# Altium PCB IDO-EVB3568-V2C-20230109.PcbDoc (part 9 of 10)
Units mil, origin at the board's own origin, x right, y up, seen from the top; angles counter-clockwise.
Board outline 5318 x 3544 mil, 2 copper layers (TOP, BOTTOM), stack 6.8 mil thick; 790 components, 626 nets, 2890 pads, 1922 vias.
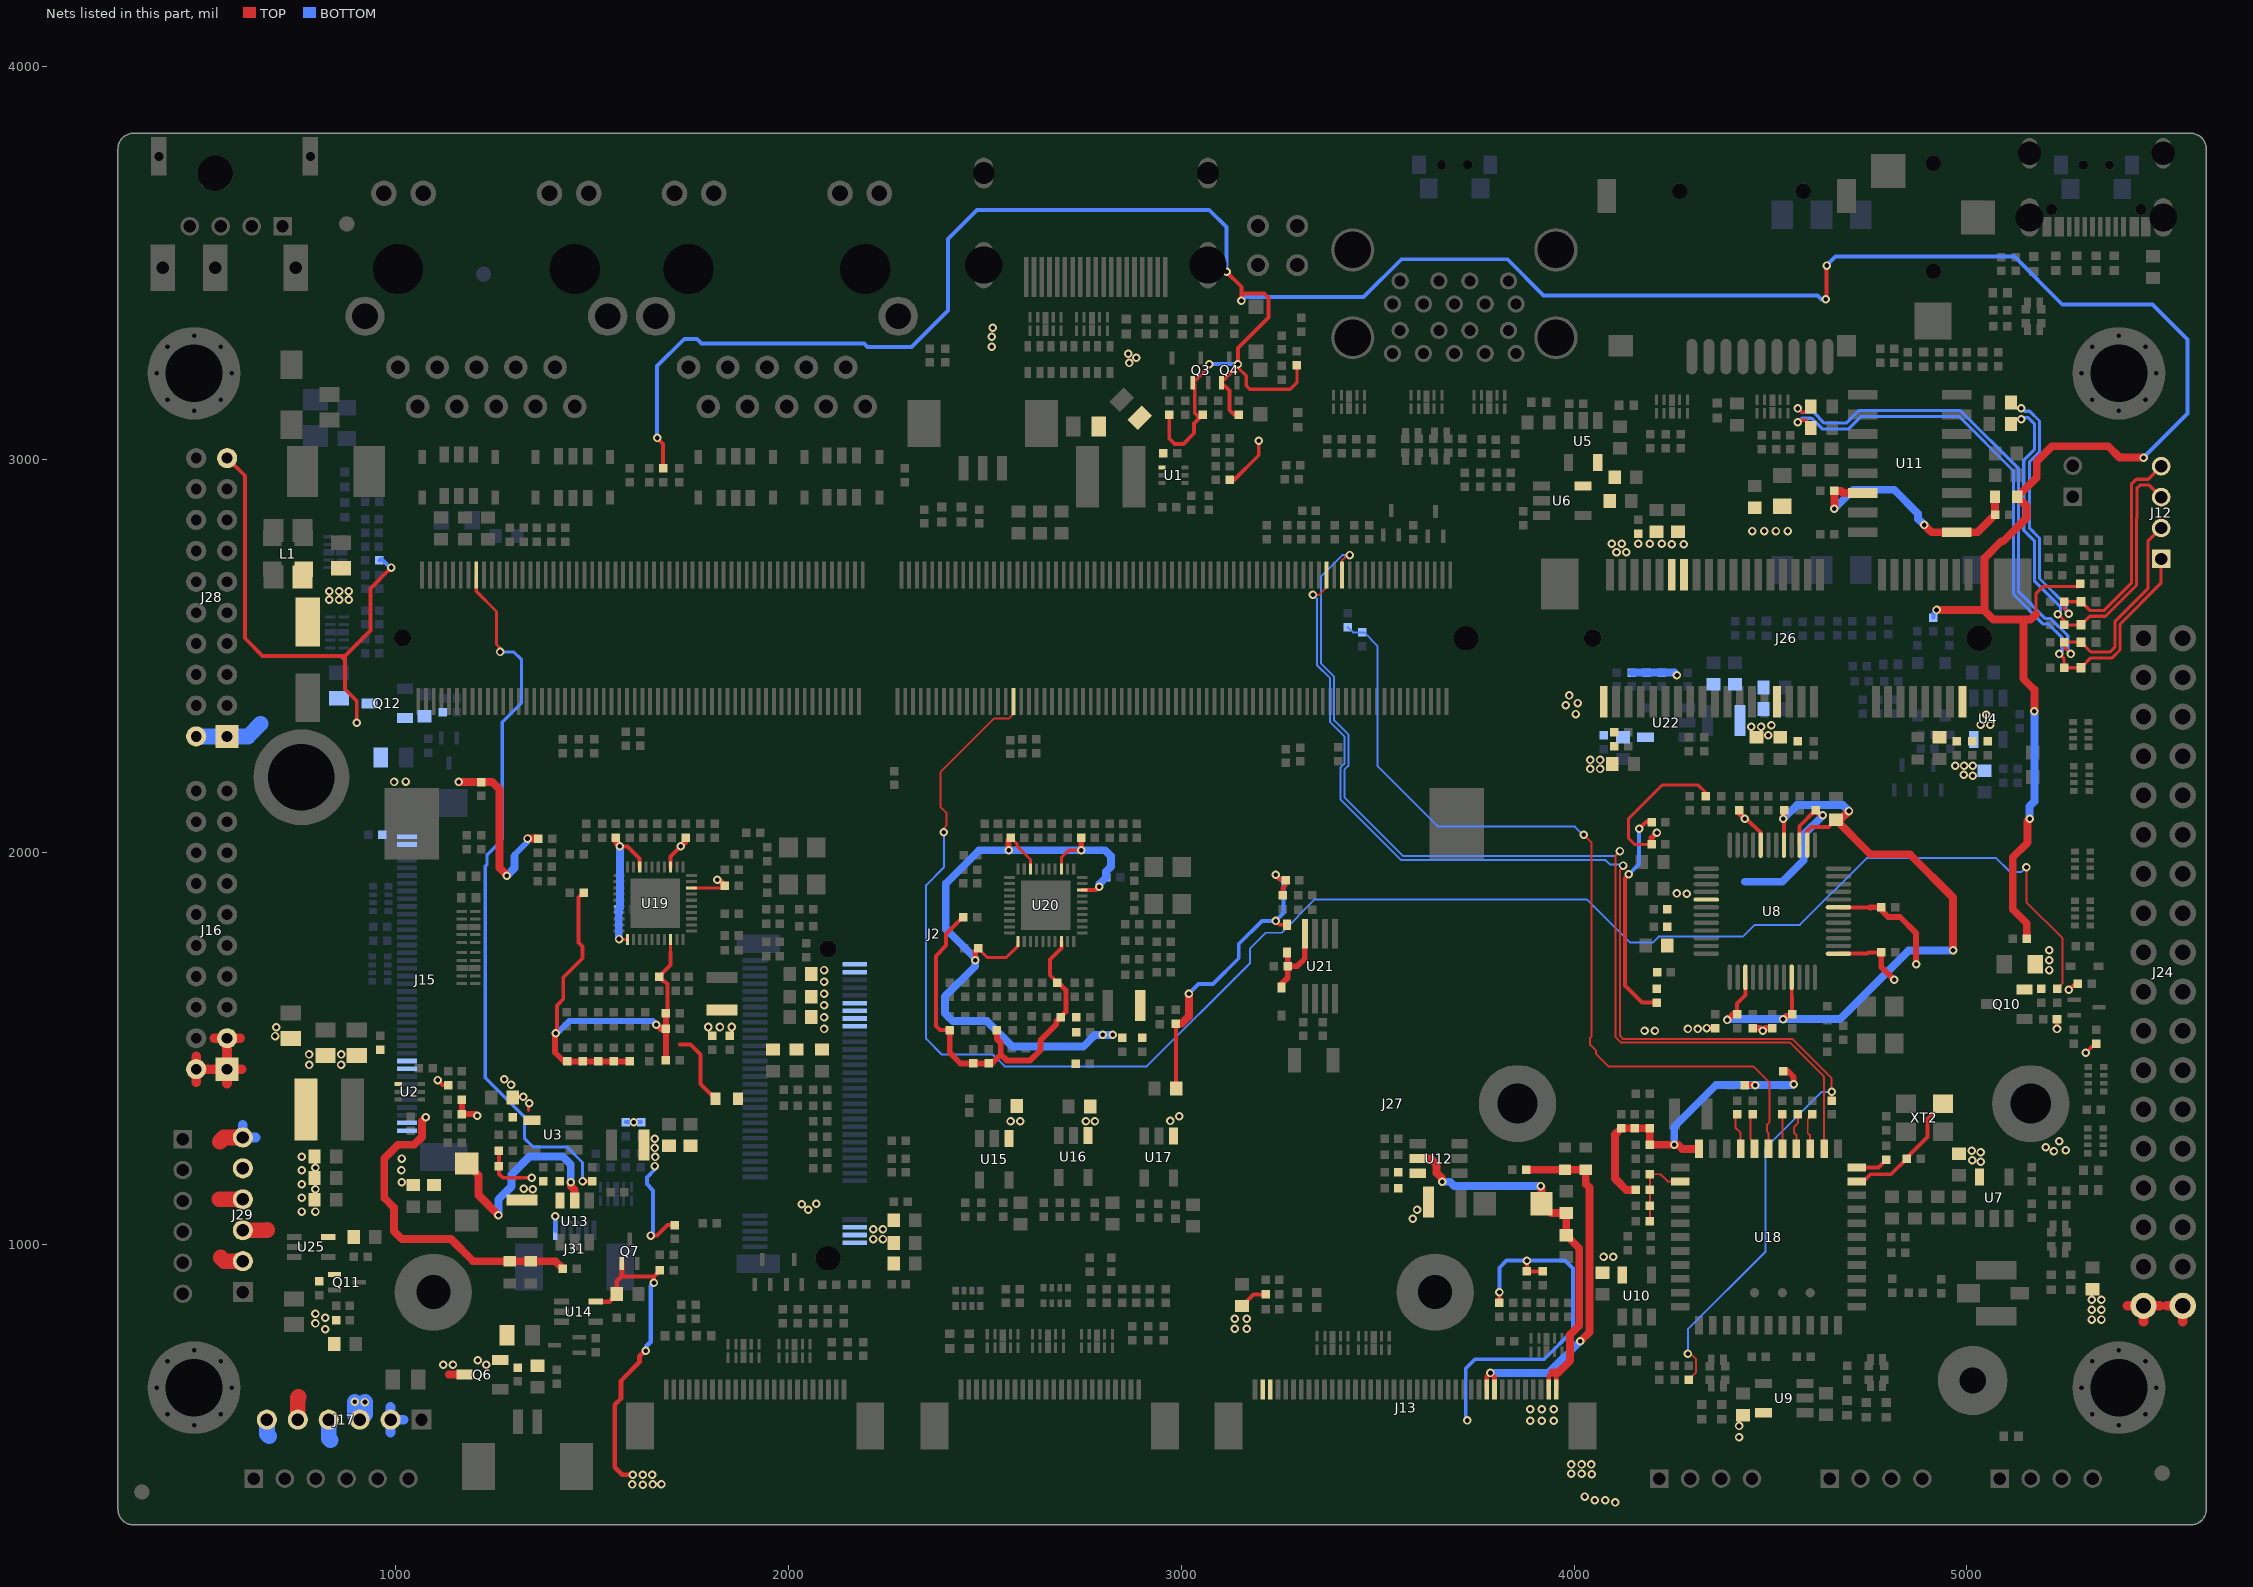
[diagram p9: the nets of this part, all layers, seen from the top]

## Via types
v1: diameter 21.65, hole 11.81, TOP to BOTTOM, 1878 vias
v2: diameter 17.72, hole 7.87, TOP to BOTTOM, 44 vias

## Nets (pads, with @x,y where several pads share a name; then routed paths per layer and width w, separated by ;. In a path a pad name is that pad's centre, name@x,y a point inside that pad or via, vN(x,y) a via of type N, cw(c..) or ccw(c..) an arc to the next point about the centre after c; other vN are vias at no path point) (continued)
VCC_1V8_HUB: C50.2 C60.2 C61.2 C62.2 U8.3 U8.9 U8.26 U8.29 | length 1861.5
  TOP w10: C61.2@4415,1587.72 4415,1615 4436.1,1636.1 U8.3@4436.1,1681.7 ; v1(4532.5,2085) 4534.5,2083 U8.29@4534.5,2018.3 ; U8.9@4554.2,1681.7 4554.2,1630.8 4555,1630 C60.2@4555,1587.72 ; U8.26@4593.6,2018.3 4593.6,2053.6 4604,2064 4648.56,2064 C50.2@4667,2082.44
  TOP w15: v1(4390,1573) 4404.72,1587.72 C61.2@4415,1587.72 ; v1(4532,1575) 4540,1583 4550.28,1583 C60.2@4555,1587.72 ; v1(4532.5,2085) 4535,2087.5 C62.2@4535,2107.28
  TOP w20: v1(4700,2105) 4677.44,2082.44 C50.2@4667,2082.44 4754.44,1995 4855,1995 4965,1885 v1(4965,1750)
  BOTTOM w20: v1(4390,1573) 4392,1575 v1(4532,1575) 4677,1575 4852,1750 v1(4965,1750) ; v1(4532.5,2085) 4567.5,2120 4685,2120 v1(4700,2105)
VCC_3V3: J2.245 R14.1 | length 1829
  TOP w8: J2.245@1204.33,2706.42 1204.33,2664.67 1256,2613 1256,2529 1265,2520 v1(1265,2510) ; v1(1475,1162.28) R14.1@1500,1162.28
  BOTTOM w8: v1(1265,2510) 1300,2510 1320,2490 1320,2381 1270.5,2331.5 1270.5,2032.52 1232,1994.02 1232,1969 1227.17,1964.17 1227.17,1425.83 1327,1326 1327,1272 1350,1249 1436,1249 1475,1210 v1(1475,1162.28)
VCC_3V3_HUB: C54.2 C55.2 C56.2 C57.2 C58.2 C59.2 R54.2 R55.2 R58.2 R59.1 R61.2 R65.1 R66.2 R76.2 U8.13 U8.19 U8.27 U8.32 U8.41 | length 1530.9
  TOP w8: R65.1@4197.28,2020 4154,2020 4139,2035 4139,2086 4224,2171 4316,2171 4335,2152 R66.2@4335,2142.72
  TOP w10: v1(4435,2085) 4439,2085 4475.5,2048.5 U8.32@4475.5,2018.3 ; U8.27@4573.9,2018.3 4573.9,2066.18 C58.2@4615,2107.28 ; U8.13@4673.3,1741.7 4746.7,1741.7 4750,1745 C57.2@4782.28,1745 ; U8.19@4673.3,1859.8 4754,1859.8
  TOP w15: R65.1@4197.28,2020 4197.28,2036.28 v1(4211,2050) ; v1(4337.72,1552.28) R58.2@4360,1552.28 ; C55.2@4420,2107.28 4420,2100 v1(4435,2085) ; R54.2@4455,1552.28 4472.72,1552.28 v1(4480,1545) 4487.28,1552.28 R55.2@4505,1552.28 ; C58.2@4615,2107.28 4628.14,2094.14 v1(4633.14,2094.14) ; 4754,1859.8 4755,1859.8 4755.2,1860 C59.2@4782.28,1860 4782.28,1852.72 4800,1835 4830,1835 4871,1794 v1(4871,1715) ; C57.2@4782.28,1745 4782.28,1707.72 v1(4815,1675)
  BOTTOM w20: 4435,1925 4530,1925 4585,1980 4585,2045 4633.14,2093.14 v1(4633.14,2094.14)
  other v1: 4290,1550 4315,1550 4287,1894 4261,1895
VCC_3V8: C190.2 C191.2 C192.2 C193.2 C194.2 C195.2 C196.2 C197.2 C198.2 C199.2 C200.2 C201.2 C202.2 C203.2 C204.2 C207.2 C208.2 C209.2 J26.2 J26.24 J26.39 J26.41 J26.52 L24.2 R342.2 R343.2 | length 117.8
  BOTTOM w20: C207.2@4147,2457.72 R343.2@4185,2457.72 C203.2@4223,2457.72 4255.28,2457.72 v1(4262,2451)
  other v1: 4041,2212 4066,2212 4041,2235 4066,2235 4494,2298 4451,2320 4476,2320 4502.65,2323.44 5035,2325 5060,2325 5050,2350 4249,2784 4279,2784 4163,2786 4193,2786 4223,2786
VCC_5V: C17.2 C18.2 C19.2 C20.2 C22.2 C23.2 C33.1 C37.1 C40.1 C43.1 C47.1 C53.1 C82.2 C83.2 C88.2 C89.2 C94.2 C177.1 C205.2 C206.2 C244.2 C248.2 J17.3 J24.35 J24.36 J29.3 L3.2 L15.1 L20.1 Q7.1 Q11.1 R11.2 R86.1 R133.1 R388.1 U3.4 U4.5 U5.5 U6.5 U7.5 U9.5 U10.5 U12.6 U13.6 U14.5 U22.4 U25.5 | length 1322.3
  TOP w5: C22.2@1297.56,1375 1322,1375 v1(1324,1377)
  TOP w8: 1337,1342 1337,1359 v1(1339,1361)
  TOP w10: 1575.32,920 1657.28,920 ; v1(1657,904) 1657,919.72 1657.28,920 ; R133.1@1672.28,935 1657.28,920
  TOP w12: U14.5@1508.31,855.59 1543.59,855.59 1562.44,874.44 C94.2@1562.44,875 1562.44,907.12 1575.32,920 Q7.1@1575.32,952.5 ; v1(1603,415) 1576,415 1557,434 1557,593 1573,609 1573,654 1620,701 1620,716 1632,728 1633.74,728 v1(1636.24,730.5)
  TOP w15: R11.2@1167.72,1333 C17.2@1167.72,1370 ; R11.2@1167.72,1333 1203.03,1332.97 v1(1207,1329)
  TOP w25: 5409.53,845 J24.35@5450,845 ; 5450,804.53 J24.35@5450,845 ; 5490.47,845 J24.35@5450,845 ; 5509.53,845 J24.36@5550,845 5550,804.53
  TOP w40: J29.3@610,1037.48 671.48,1037.48 672,1038
  BOTTOM w12: v1(1636.24,730.5) 1637,731.26 1637,742 1649,754 1649,896 v1(1657,904)
  BOTTOM w40: v1(895,601) 895,567.52 J17.3@907.52,555 921,568.48 v1(921,600)
  other v1: 1628,389 1602,390 1654,390 1676,391 1628,415 1653,415 4045,416 3993,417 4019,417 3993,441 4019,441 4044,441 4420,510 4420,539 3888,552 3918,552 3948,552 3888,582 3918,582 3948,582 5318,810 5343,810 5318,835 5343,835 5318,860 5343,860 4075,970 4100,970 3589,1067 760,1085 795,1085 3600,1090 760,1120 795,1142 1348,1142 1325,1143 760,1155 760,1190 795,1197 5036,1212 5014,1216 760,1225 5035,1236 5013,1240 1293,1408 1276,1422 5015,2195 4992,2197 4971,2220 4993,2220 5015,2220 4004,2352 3979,2374 4009,2380 3987.43,2399.29 4108,2764 4133,2764 4096,2786 4121,2786 4454,2818 4484,2818 4514,2818 4544,2818
VCC_12V: C3.1 C4.2 C5.2 C6.2 C7.2 C14.2 C15.2 C16.2 L1.4 R1.2 R3.2 U1.1 U2.1 | length 137.6
  TOP w10: R3.2@3122.72,2948 3134,2948 3197,3011 3197,3047.71 v1(3197.34,3048.05)
  other v1: 779.56,1458.35 860,1459 778.58,1485 861,1485 830,2643 855,2643 880,2643 830,2665 855,2665 880,2665 2867,3246 2885,3259 2865,3269 2517,3287 2517,3313 2520,3336
VCC_EDP_OUT: C245.2 C246.2 J29.2 J29.4 J29.6 Q12.2 R391.2 | length 248.5
  TOP w40: 550,1116 550.22,1116.22 J29.4@610,1116.22 ; 551,1263 561.7,1273.7 J29.6@610,1273.7 ; 554,968 563.26,958.74 J29.2@610,958.74
  BOTTOM w25: 610,1306.29 J29.6@610,1273.7 642.59,1273.7
VCC_EDP_OUT_: C247.2 J28.1 J28.2 Q12.3 | length 177
  BOTTOM w40: J28.2@491.26,2295 J28.1@570,2295 623,2295 655,2327
VCC_LEDA_TX0: C86.2 C87.2 D50.C J15.1 J15.2 U13.5 | length 556
  TOP w20: D50.C@1180,1207.44 1210,1177.44 1210,1127 v1(1261,1076) ; v1(1445,1160) 1445,1150 1455,1140 U13.5@1455,1113.15
  BOTTOM w20: v1(1261,1076) 1261,1116 1294,1149 1294,1179 1340,1225 1425,1225 1445,1205 v1(1445,1160)
  other v1: 1015,1160 1014,1190 1015,1220
VCC_LEDA_TX1: C81.2 C84.2 D39.C J13.1 J13.2 U12.5 | length 1029.2
  TOP w12: J13.2@3935.24,632.01 3935.24,665.16 3945.08,675 3954.92,665.16 J13.1@3954.92,632.01
  TOP w20: U12.5@3601.85,1220 3635,1220 3650,1205 3650,1183.3 3664,1169.3 v1(3664,1161) ; v1(3915,1150) 3917.44,1147.56 D39.C@3917.44,1105 3941,1081.44 C84.2@3980,1081.44 C81.2@3980,1024.56 4013,991.56 4013,795 3990,772 3990,705 3960,675 3945.08,675
  BOTTOM w20: v1(3664,1161) 3684,1161 3695,1150 v1(3915,1150)
VCC_LEDK_TX0: J15.9 J15.10 R117.1 R119.2 R120.2 | length 836.9
  TOP w20: v1(1076,1325) 1066,1315 1066,1275 1046,1255 1005,1255 970,1220 970,1120 995,1095 995,1035 1015,1015 1140,1015 1196.46,958.54 R119.2@1290,958.54 R120.2@1343,958.54 1405.74,958.54 R117.1@1424.28,940
VCC_LEDK_TX1: J13.9 J13.10 R99.1 R101.2 R102.2 | length 956.6
  TOP w12: J13.10@3777.76,632.01 3777.76,664.76 v1(3787,674) 3797.44,663.56 J13.9@3797.44,632.01
  TOP w20: R99.1@3877.72,1191 3878.18,1191.46 R102.2@3977,1191.46 R101.2@4029.52,1191.46 4029.52,1155.48 4039,1146 4039,778 v1(4016,755)
  BOTTOM w20: v1(3787,674) 3935,674 v1(4016,755)
VCC_LVDS_OUT: C91.2 C92.2 J17.2 J17.4 J17.6 Q6.2 R134.2 | length 195.9
  BOTTOM w25: 986.26,522.41 J17.2@986.26,555 ; 986.26,587.59 J17.2@986.26,555 ; 1018.85,555 J17.2@986.26,555
  BOTTOM w40: J17.6@671.3,555 671.3,518.7 677,513 ; J17.4@828.78,555 828.78,507.22 833,503
  other v1: 1230,695 1208,706
VCC_LVDS_OUT_: C93.2 J16.1 J16.2 J16.3 Q6.3 | length 381.4
  TOP w20: 1135,670 Q6.3@1174.72,670
  TOP w25: 491.26,1415.01 J16.2@491.26,1447.6 ; 491.26,1480.19 J16.2@491.26,1447.6 ; 523.85,1447.6 J16.2@491.26,1447.6 ; 533.47,1447.6 J16.1@570,1447.6 ; 537.41,1526.34 J16.3@570,1526.34 ; 570,1411.07 J16.1@570,1447.6 ; 570,1484.13 J16.1@570,1447.6 ; 570,1493.74 J16.3@570,1526.34 ; 602.59,1526.34 J16.3@570,1526.34 ; 606.53,1447.6 J16.1@570,1447.6
  other v1: 1120,695 1145,695 692,1532 695,1554
VCCA_CODEC: C67.2 C68.2 R85.2 U11.6 U11.9 | length 665.3
  TOP w20: v1(4662.72,2875) C67.2@4662.72,2920 4680,2920 4685.23,2914.78 4702.49,2914.78 4702.72,2915 U11.6@4735,2915 ; v1(4891.5,2833.5) 4910,2815 U11.9@4975,2815 5027.28,2815 C68.2@5072.28,2860 5071.46,2860.82 R85.2@5071.46,2905
  BOTTOM w20: v1(4662.72,2875) 4710.72,2923 4815,2923 4876,2862 4876,2849 v1(4891.5,2833.5)
VCCIO_PHY0: C144.2 C145.2 C146.2 R236.2 R238.2 R240.2 R243.2 R246.2 R249.2 R250.2 U19.28 | length 1277.4
  TOP w8: 1699.37,1745 U19.28@1699.37,1777.48
  TOP w10: v1(1407,1539) 1407,1547 1410,1550 1410,1610 1426,1626 1426,1681 1475,1730 1475,1760 1465,1770 1465,1884.28 R249.2@1477.72,1897 ; C145.2@1687.28,1590 1691,1593.72 1691,1664 1682.5,1672.5 1680.22,1672.5 C146.2@1670,1682.72 1670,1683.72 1699.37,1713.09 1699.37,1745
  TOP w15: v1(1407,1539) 1405,1537 1405,1490 1427.72,1467.28 R236.2@1436,1467.28 R246.2@1475,1467.28 R243.2@1515,1467.28 R240.2@1555,1467.28 R238.2@1595,1467.28 ; v1(1663,1561) 1674,1550 C144.2@1687.28,1550 ; R250.2@1687.28,1470 C144.2@1687.28,1550 ; C145.2@1687.28,1590 C144.2@1687.28,1550
  BOTTOM w15: v1(1407,1539) 1413,1545 1416,1545 1441,1570 1654,1570 v1(1663,1561)
VCCIO_PHY1: C168.1 C169.2 C170.2 R283.2 R285.2 R288.2 R291.2 R294.2 R297.2 R298.2 U20.28 | length 1072.2
  TOP w10: R283.2@2410,1547.28 2385.72,1547.28 2375,1558 2375,1736 2401,1762 2401,1791.72 R297.2@2444.28,1835 ; C170.2@2684,1667.72 2665,1686.72 2665,1727 2694.37,1756.37 U20.28@2694.37,1772.48
  TOP w12: C170.2@2684,1667.72 2687.28,1667.72 2706,1649 2706,1593.28 R285.2@2692.72,1580
  TOP w15: R283.2@2410,1547.28 2410,1490 2437.72,1462.28 R294.2@2470,1462.28 R291.2@2510,1462.28 2517.28,1462.28 2540,1485 ; R288.2@2530,1547.28 2530,1525 2540,1515 2540,1485 ; R285.2@2692.72,1580 2681.35,1568.63 2681.35,1561.35 2641,1521 2641,1496 2615,1470 2555,1470 2540,1485
VCCIO_WL: C120.2 C121.2 C122.2 R180.1 R185.1 R200.2 R204.1 U18.22 | length 918.4
  TOP w15: R180.1@4434.72,1407 v1(4461.37,1407) ; R185.1@4532,1442.72 4544,1442.72 4559,1427.72 v1(4559,1409)
  TOP w20: R204.1@4157.28,1140 4133,1140 4104,1169 4104,1281.28 R200.2@4120,1297.28 C122.2@4155,1297.28 C120.2@4193,1297.28 4192.72,1297 C121.2@4192.72,1255 v1(4255,1255) 4265,1255 4275.59,1244.41 U18.22@4317.83,1244.41
  BOTTOM w20: v1(4255,1255) 4255,1301 4361,1407 v1(4461.37,1407) 4557,1407 v1(4559,1409)
VDD3V3_PCIE30: C214.2 C215.2 C216.2 C217.2 C218.2 C219.2 C220.2 C221.2 C222.2 J27.2 J27.4 J27.12 J27.14 J27.16 J27.18 J27.70 J27.72 J27.74 R359.2
  other v1: 2215,1015 2240,1015 2215,1040 2240,1040 2050,1090 2033,1104 2070,1105 2090,1550 2090,1580 2090,1610 2090,1640 2090,1670 2090,1700
VDD10_PHY0: C136.2 C137.2 C138.2 C139.2 C140.2 C141.2 L22.2 U19.3 U19.8 U19.21 U19.38 | length 574.1
  TOP w8: v1(1568,1779) 1569,1779 1570.52,1777.48 U19.21@1589.13,1777.48 ; U19.38@1752.52,1909.37 1831.65,1909.37 C139.2@1837.28,1915
  TOP w10: v1(1570,2015) 1590,2015 1620.63,1984.37 U19.8@1620.63,1962.52 ; U19.3@1699.37,1962.52 1699.37,1989.37 v1(1725,2015)
  TOP w15: C140.2@1560,2037.28 1560,2025 v1(1570,2015) ; v1(1725,2015) 1738,2028 C141.2@1738,2037.28 ; v1(1818,1930) 1822.28,1930 C139.2@1837.28,1915
  BOTTOM w20: v1(1568,1779) 1567.28,1779.72 C138.2@1567.28,1855 1570,1857.72 v1(1570,2015)
  other v1: 1795,1555 1825,1555 1855,1555
VDD10_PHY1: C160.2 C161.2 C162.2 C163.2 C164.1 C165.2 L23.2 U20.3 U20.8 U20.21 U20.38 | length 1888.3
  TOP w8: C162.2@2482.72,1755 2505.72,1732 2554,1732 2584.13,1762.13 U20.21@2584.13,1772.48 ; C165.2@2566,2037.28 2581.14,2022.14 2581.14,2016.14 2615.63,1981.65 U20.8@2615.63,1957.52 ; U20.3@2694.37,1957.52 2694.37,1986.65 2712.72,2005 v1(2745,2005)
  TOP w10: U20.38@2747.52,1904.37 2783.37,1904.37 v1(2791,1912)
  TOP w15: v1(2475,1725) 2475,1747.28 C162.2@2482.72,1755 ; v1(2560,2005) 2560,2031.28 C165.2@2566,2037.28 ; v1(2745,2005) C164.1@2745,2037.28
  BOTTOM w20: v1(2791,1912) 2791,1918.72 C163.2@2808.28,1936 2808.28,1951.28 2820.64,1963.64 2820.64,1990 2805.64,2005 v1(2745,2005) v1(2560,2005) 2485,2005 2400,1920 2400,1805 2475,1730 v1(2475,1725) 2475,1710 2398,1633 2398,1590 2418,1570 2505,1570 2570,1505 2750,1505 2780,1535 v1(2800,1535) v1(2825,1535)
VDD_3V3: C21.2 C24.2 C25.2 C79.2 C101.2 C105.2 C109.2 C123.2 C124.2 C243.2 C260.2 D69.A J13.38 J13.39 J15.38 J15.39 J17.5 J28.19 J29.5 J31.1 L4.2 Q3.1 Q4.1 Q10.2 R10.1 R15.2 R37.2 R74.2 R76.1 R80.1 R85.1 R92.2 R93.2 R98.1 R103.1 R105.1 R109.2 R111.2 R112.2 R121.1 R132.1 R202.1 R203.2 R258.1 R267.2 R306.1 R326.2 R327.2 R359.1 R384.1 R387.1 R400.1 R401.1 R409.1 R415.1 U15.1 U16.1 U17.1 | length 13477.3
  TOP w8: v1@3144,3239.59 3144,3234 3165,3213 3165,3188 3174,3179 3277,3179 3294,3196 R10.1@3294,3240.28 ; 5176,2606 5176,2658 5195,2677 R80.1@5282.28,2677
  TOP w10: J28.19@570,3003.66 615,2958.66 615,2545 660,2500 860,2500 ; v1(900,2330) 900,2385 870,2415 870,2490 ; v1(988,2725) 935,2672 935,2565 870,2500 ; v1(1106,1420) 1118.72,1407.28 R409.1@1133,1407.28 ; R15.2@1262.28,1240 C24.2@1262.28,1200 1262.28,1180.83 1272,1171.11 v1(1346,1171.11) ; v1(1649,1024) 1665,1024 1691.72,1050.72 R132.1@1710,1050.72 ; v1(1665,3055) 1680,3040 R267.2@1680,2977.72 ; 1722.72,1510 1750,1510 1775,1485 1775,1410 R359.1@1810,1375 ; R109.2@2969,3114.28 2969,3054 2983,3040 3005,3040 3032,3067 3032,3091.28 R103.1@3046.53,3105.81 ; R306.1@2986,1563.28 2986.56,1562.72 C109.2@2986.56,1398 ; R103.1@3055,3114.28 R103.1@3046.53,3105.81 ; v1(3071,3243) 3071,3237.19 Q3.1@3029.32,3195.5 3034,3190.82 3034,3118.35 R103.1@3046.53,3105.81 ; v1(3115,3478) 3153,3440 3153,3423 ; R105.1@3146,3114.28 3134,3114.28 3122,3126.28 3122,3175.82 Q4.1@3102.32,3195.5 3102.32,3197.91 3144,3239.59 v1(3144,3243) 3144,3284 3222,3362 3222,3412 3211,3423 3153,3423 ; v1(3153,3404) 3153,3423 ; C79.2@3154,844.44 3183.56,874 R98.1@3214.28,874 ; v1(3240,1825) 3249.57,1815.43 3258.13,1815.43 D69.A@3269,1815.43 ; v1(3240,1943) 3240,1940.72 3250.36,1930.36 3263.92,1930.36 R326.2@3265.28,1929 3265.28,1915.28 3258,1908 R327.2@3258,1890.72 ; R415.1@3810,852.72 v1(3810,880) ; v1(3880,960) R93.2@3880,932.72 R92.2@3920,932.72 ; v1(4139.47,1944) 4129.5,1934.03 4129.5,1660.5 4172.72,1617.28 R76.1@4210,1617.28 ; v1(4165.5,2059.5) 4183,2077 R74.2@4197.28,2077 ; v1(4641,3408) 4643,3410 v1(4643,3494) ; v1(5229.72,1550) C124.2@5229.72,1575 ; v1(5260,1650) 5275,1665 R401.1@5282.28,1665 ; R80.1@5282.28,2677 R80.1@5289.28,2684 ; v1(5303,1489) 5326.28,1512.28 R400.1@5330,1512.28 ; 860,2500 870,2500 ; 860,2500 870,2490 ; 870,2490 870,2500
  TOP w20: v1(1160,2179) 1216.72,2179 R121.1@1217,2178.72 1245,2178.72 1264,2159.72 1264,1960 1282.5,1941.5 v1(1282.5,1940.5) ; v1(1335,2035) R258.1@1362.28,2035 ; R306.1@2986,1563.28 3000.28,1563.28 3019,1582 3019,1639.67 v1(3019.33,1640) ; v1(4923,2617) 5043,2617 5045,2615 ; C123.2@5152.72,1780 5152.72,1819.28 5117,1855 5117,1987 5155,2025 5155,2080.11 v1(5159.94,2085.06) ; v1(5172,2359) 5172,2414 5144,2442 5144,2592.5 ; 5176,2606 5162.5,2592.5 5144,2592.5 ; v1(5450,3005) 5389,3005 5360,3034 5217,3034 5178,2995 5178,2954.46 R85.1@5128.54,2905 5152,2881.54 5152,2851 5093,2792 5088,2792 5045,2749 5045,2615 ; 5045,2615 5067.5,2592.5 5144,2592.5
  TOP w40: J17.5@750.04,555 750.04,611.04 752,613
  BOTTOM w10: R384.1@957.72,2743 961.72,2747 963,2747 985,2725 v1(988,2725) ; v1(1160,2179) v1@1163,2182 ; 1302,1989.25 1302,1994 ; R111.2@1585,1312.72 v1(1605,1312.72) R112.2@1624,1312.72 ; v1(1649,1024) 1655,1030 1655,1138.89 1639.17,1154.72 1639.17,1171.97 1659,1191.8 v1(1659,1201) ; v1(1665,3055) 1665,3238 1734,3307 1767,3307 1778,3296 2192,3296 2201,3287 2313,3287 2406,3380 2406,3562 2480,3636 3071,3636 3115,3592 v1(3115,3478) ; v1(3019.33,1640) 3043.33,1664 3080,1664 3146,1730 3146,1766 3205,1825 v1(3240,1825) 3260,1845 3260,1923 v1(3240,1943) ; v1(3071,3243) v1(3144,3243) ; v1(3153,3404) 3163,3414 3464,3414 3560,3510 3830,3510 3922.5,3417.5 4620,3417.5 4629.5,3408 v1(4641,3408) ; v1(3728,553) 3727.89,553.11 3727.89,557.54 3724.17,561.26 3724.17,685.7 3747.47,709 3924,709 3997,782 3997,940 3977,960 v1(3880,960) 3828,960 3810,942 v1(3810,880) ; v1(4139.47,1944) 4165.5,1970.03 v1(4165.5,2059.5) ; v1(4643,3494) 4666,3517 5121,3517 5243,3395 5473,3395 5562,3306 5562,3117 v1(5450,3005) ; R37.2@4915,2597.72 4915,2609 v1(4923,2617)
  BOTTOM w12: J31.1@1405.79,1037.01 v1(1405.79,1073)
  BOTTOM w15: 1302,1994 1335,2027 v1(1335,2035)
  BOTTOM w20: v1(1282.5,1940.5) 1302,1960 1302,1989.25 ; v1(5159.94,2085.06) 5159.94,2116.95 5172,2129 v1(5172,2359)
  other v1: 4105.02,344.22 4052.35,350 4079,350 4027.39,359.35 820,785 3136,787 3166,787 795,800 3136,812 3166,812 820,815 795,825 1660,1224 5222,1239 5252,1241 1659,1247 5201,1249 5235,1264 1659,1270 2565,1315 2590,1315 2757,1315 2780,1315 2971.37,1315.67 2995,1328 4179.35,1545 4206,1545 5210,1700 5210,1725 5210,1750 995,2179 1025,2180
VDD_RTC: C181.2 D69.C D70.C U21.8 | length 211.4
  TOP w14: C181.2@3270.72,1710 3295,1710 3314.61,1729.61 U21.8@3314.61,1792.68
  TOP w15: D70.C@3255,1655.43 3255,1665 3270.72,1680.72 C181.2@3270.72,1710 3270.72,1742.85 D69.C@3269,1744.57
VOLN: C73.1 D30.2 J12.1 L11.2 | length 1687.2
  TOP w8: v1(4570,3095) 4575,3100 4590,3100 4602.44,3087.56 L11.2@4602.44,3080 ; v1(5235,2505) 5247.72,2492.28 C73.1@5247.72,2470 D30.2@5291.1,2470 5316.1,2495 5370,2495 5390,2515 5390,2581 5495,2686 J12.1@5495,2746.89
  BOTTOM w8: v1(4570,3095) 4580,3105 4605,3105 4632,3078 4699,3078 4731,3110 4980,3110 5119,2971 5119,2657 5195,2581 5208,2581 5243,2546 5243,2513 v1(5235,2505)
VOLP: C74.1 D31.2 J12.2 L12.2 | length 1765.1
  TOP w8: v1(4570,3130) 4579.34,3120.66 4590.66,3120.66 4602.44,3132.44 L12.2@4602.44,3135 ; v1(5265,2505) 5247.72,2522.28 C74.1@5247.72,2535 D31.2@5291.1,2535 5316.1,2510 5365,2510 5377,2522 5377,2587 5461,2671 5461,2791.63 J12.2@5495,2825.63
  BOTTOM w8: v1(4570,3130) 4580,3120 4610,3120 4637.32,3092.68 4692.68,3092.68 4725,3125 4983.38,3125 5132,2976.38 5132,2663 5200,2595 5214,2595 5257,2552 5257,2513 v1(5265,2505)
VORN: C76.1 D32.2 J12.3 L13.2 | length 1196.6
  TOP w8: L13.2@5112.56,3090 5125.62,3103.06 5138.94,3103.06 v1(5139,3103) ; v1(5232,2606) 5247.72,2590.28 C76.1@5247.72,2579 D32.2@5291.1,2579 5313.1,2601 5353,2601 5355,2603 5355.38,2603 5432,2679.62 5432,2850.39 5433,2851.39 5433,2927 5441,2935 5464.37,2935 J12.3@5495,2904.37
  BOTTOM w8: v1(5139,3103) 5143.34,3107.34 5155.66,3107.34 5172,3091 5172,3025.39 5145,2998.39 5145,2820.04 5171.83,2793.21 ; 5171.83,2793.17 5172,2793 5172,2691 5238.84,2624.16 5238.84,2612.84 v1(5232,2606)
VORP: C77.1 D33.2 J12.4 L14.2 | length 1226.9
  TOP w8: L14.2@5112.56,3145 5126.56,3131 v1(5139,3131) ; v1(5260,2607) 5247.72,2619.28 C77.1@5247.72,2638 D33.2@5291.1,2638 5313.1,2616 5350,2616 5419,2685 5419,2937.11 5431.89,2950 5461.89,2950 J12.4@5495,2983.11
  BOTTOM w8: v1(5139,3131) 5147,3123 5160,3123 5185,3098 5185,3020 5160,2995 5160,2825 5185,2800 5185,2697 5252,2630 5252,2615 v1(5260,2607)
WIFI1T1R_CLK: C112.2 R187.2 U18.17 | length 2218
  TOP w5: v1(4025,2045) 4044,2026 4044,1530.57 4041,1527.57 4041,1509.49 4056.33,1494.16 4056.33,1485.67 4087.01,1454.99 4455.86,1454.99 4498,1412.86 4498,1313 4491.67,1306.67 4491.67,1288.33 4495,1285 U18.17@4495,1244.41
  BOTTOM w5: R187.2@3424,2573.28 3437.56,2559.72 C112.2@3461,2559.72 3465.28,2559.72 3499.33,2525.67 3499.33,2219.95 3654.28,2065 4002.26,2065 4022.26,2045 v1(4025,2045)
WIFI1T1R_CMD: R186.2 U18.16 | length 88
  TOP w5: R186.2@4530,1332.28 4530.43,1331.85 U18.16@4530.43,1244.41
WIFI1T1R_D0: R181.2 U18.18 | length 94.7
  TOP w5: R181.2@4455,1332.28 4449,1326.28 4449,1271 4459.57,1260.43 U18.18@4459.57,1244.41
WIFI1T1R_D1: R182.2 U18.19 | length 95
  TOP w5: R182.2@4415,1332.28 4411,1328.28 4411,1299 4424.13,1285.87 U18.19@4424.13,1244.41
WIFI1T1R_D2: R183.2 U18.14 | length 95.5
  TOP w5: U18.14@4601.3,1244.41 4601.3,1278.7 4595,1285 4595,1320.28 R183.2@4607,1332.28
WIFI1T1R_D3: R184.2 U18.15 | length 94.4
  TOP w5: U18.15@4565.87,1244.41 4565.87,1280 4560,1285.87 4560,1300 4570,1310 R184.2@4570,1332.28
WIFI1T1R_XTAL_IN: C114.1 U18.10 XT2.3 | length 329.5
  TOP w10: U18.10@4719.41,1161.73 4736.73,1161.73 4755,1180 4807.28,1180 C114.1@4847.28,1220 4847.28,1222.28 4900,1275 4900,1320.19 XT2.3@4939.24,1359.43
WIFI1T1R_XTAL_OUT: R191.2 U18.11 | length 83.9
  TOP w10: U18.11@4719.41,1197.17 4774.89,1197.17 R191.2@4795,1217.28
WIFI_PWREN_L_GPIO0_B7: J2.114 R207.2 | length 4522.7
  TOP w5: v1(2395,2051) 2396,2052 2396,2062 2402.33,2068.33 2402.33,2099.74 2386,2116.06 2386,2203.57 2522.43,2340 2560,2340 2572.44,2352.44 J2.114@2572.44,2383.58 ; v1(5152,1962) 5152,1873 5244,1781 5244,1666.72 R207.2@5230,1652.72
  BOTTOM w5: v1(2395,2051) 2395.5,2050.5 2395.5,1961.64 2350,1916.14 2350,1525 2390,1485 2520,1485 2550,1455 2912,1455 3175,1718 3175,1755 3215,1795 3255,1795 3340,1880 4032.43,1880 4044.14,1868.29 4050,1862.43 4142.43,1770 4200,1770 4215,1785 4430,1785 4460,1815 4575,1815 4745,1985 5075,1985 5110,1950 5140,1950 v1(5152,1962)
WIFI_REG_ON_H_GPIO3_D5: J2.33 R196.1 R210.1 | length 3419.4
  TOP w5: v1(3335,2656) 3336,2655 3350,2655 3369.68,2674.68 J2.33@3369.68,2706.42 ; v1(4124.58,1966.11) 4124.58,1962.58 4117,1955 4117,1532.49 4124.49,1525 4445.14,1525 4494.85,1525 4555,1525 4656,1424 v1(4656,1390) R196.1@4656,1367.72 ; v1(4290,723) 4297,723 4311,709 4311,676.28 R210.1@4292,657.28
  BOTTOM w5: v1(3335,2656) 3345,2646 3345,2476.86 3379,2442.86 3379,2331 3415,2295 3415,2225 3405,2215 3405,2135 3560,1980 4080,1980 4091,1969 4121,1969 4123.89,1966.11 v1(4124.58,1966.11) ; v1(4290,723) 4290,785 4487,982 4487,1246 4631,1390 v1(4656,1390)
WIFI_WAKE_HOST_H_GPIO3_D4: J2.29 U18.13 | length 2759.5
  TOP w5: J2.29@3409.05,2706.42 3409.05,2744.05 3421.96,2756.96 3429.04,2756.96 v1(3429.16,2756.84) ; v1(4116.8,2003.12) 4106,1992.32 4106,1529.35 4120.35,1515 4449.29,1515 4490.71,1515 4550,1515 4636.73,1428.27 U18.13@4636.73,1244.41
  BOTTOM w5: v1(3429.16,2756.84) 3409.84,2756.84 3355,2702 3355,2481 3389,2447 3389,2336 3425,2300 3425,2220 3415,2210 3415,2140 3565,1990 4104,1990 4116.88,2002.88 4116.88,2003.03 v1(4116.8,2003.12)
WIFIBT_32KIN_1T1R: C126.2 R204.2 R205.2 R206.2 U18.24 | length 205.4
  TOP w5: R205.2@4192.72,1060 R206.2@4192.72,1100 R204.2@4192.72,1140 C126.2@4192.72,1180 4220,1180 4238.27,1161.73 U18.24@4270.59,1161.73
pads on no net: D3.1 D3.10 D81.5 D82.5 D83.5 D84.5 HOLE1. HOLE2. HOLE3. HOLE4. J1.1 J1.5 J1.6 J2. J2.160 J2.162 J2.164 J2.166 J2.168 J2.170 J2.172 J2.174 J2.176 J2.178 J2.239 J2.241 J2.243 J3. J5.A8 J5.B8 J5.NC1 J5.NC2 J10. J13.3 J13.8 J13.12 J13.13 J13.14 J13.15 J13.35 J13.40 J15.3 J15.8 J15.12 J15.13 J15.14 J15.15 J15.35 J15.40 J16.4 J16.19 J16.20 J20.20 J20.21 J20.23 J20.24 J22. J23. J26.1 J26.3 J26.5 J26.6 J26.7 J26.11 J26.13 J26.16 J26.17 J26.19 J26.20 J26.28 J26.30 J26.32 J26.44 J26.45 J26.46 J26.47 J26.48 J26.49 J26.51 J26.53 J26.54 J27.5 J27.6 J27.7 J27.8 J27.10 J27.11 J27.13 J27.17 J27.19 J27.20 J27.22 J27.23 J27.24 J27.25 J27.26 J27.28 J27.29 J27.30 J27.31 J27.32 J27.34 J27.35 J27.36 J27.37 J27.38 J27.40 J27.42 J27.44 J27.46 J27.48 J27.56 J27.58 J27.67 J28.3 J28.5 J28.6 J28.20 MARK1.1 MARK2.1 MARK3.1 MARK4.1 SIM1.C6 SIM1.CD1 SIM1.CD2 SW1. SW2. U8.2 U8.4 U8.8 U8.43 U8.44 U8.45 U8.46 U8.47 U18.4 U18.5 U18.8 U18.25 U18.26 U18.27 U18.28 U18.30 U18.32 U18.35 U18.37 U18.38 U18.39 U18.40 U18.45 U18.46 U18.47 U19.31 U20.31 U21.3

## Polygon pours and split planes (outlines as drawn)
VCC5V_SYS on BOTTOM "BOTTOM-VCC5V_SYS" (solid, pour order 9): 1129,2815 1070,2815 1055,2830 1036,2849 1036,2877 1045,2886 1118,2886 1136,2868 1136,2822 1129,2815
VCC_EDP_OUT_ on BOTTOM "BOTTOM-VCC_EDP_OUT_" (solid, pour order 86): 955,2415 955,2370 945,2360 810,2360 795,2345 730,2345 640,2255 475,2255 460,2270 460,2320 470,2330 590,2330 680,2420 950,2420 955,2415
VCC_LVDS_OUT_ on BOTTOM "BOTTOM-VCC_LVDS_OUT_" (solid, pour order 95): 39 vertices, not listed, extent 680,660 1157,1566
VDD_3V3 on BOTTOM "BOTTOM-VDD_3V3" (solid, pour order 56): 29 vertices, not listed, extent 953,2010 1174,2201
VBAT_WL_1T1R on BOTTOM "BOTTOM-VBAT_WL_1T1R" (solid, pour order 91): 5105,1685 5105,1615 5060,1570 5030,1570 4920,1460 4920,1265 4945,1240 4945,1150 4930,1135 4891,1135 4831.5,1194.5 4831.5,1444.5 5075.5,1688.5 5101.5,1688.5 5105,1685
VCC_5V on BOTTOM "BOTTOM-VCC_5V" (solid, pour order 102): 25 vertices, not listed, extent 3565,540 4121,1120.5
VCC_5V on BOTTOM "BOTTOM-VCC_5V 1" (solid, pour order 32): 20 vertices, not listed, extent 4960,2183 5065,2315
N69853313 on BOTTOM "BOTTOM-N69853313" (solid, pour order 15): 1023,2429 1053,2429 1063,2419 1153,2419 1173,2399 1173,2389 1173,2384 1168,2379 1163,2379 1023,2379 1003,2379 998,2384 998,2424 1003,2429 1023,2429
VCC_LEDA_TX0 on BOTTOM "BOTTOM-VCC_LEDA_TX0" (solid, pour order 13): 1000,1315 1000,1180 1000,1155 1010,1145 1020,1145 1035,1160 1035,1185 1035,1255 1055,1275 1055,1315 1050,1320 1005,1320 1000,1315
VCC5V0_USB_HOST1 on BOTTOM "BOTTOM-VCC5V0_USB_HOST1" (solid, pour order 71): 18 vertices, not listed, extent 3760,3175 3910,3370
VCC5V0_USB1 on BOTTOM "BOTTOM-VCC5V0_USB1" (solid, pour order 59): 18 vertices, not listed, extent 4955,809 5228,1058
VCC5V0_USB_OTG0 on BOTTOM "BOTTOM-VCC5V0_USB_OTG0" (solid, pour order 20): 4970,2500 4970,2380 4980,2370 5025,2370 5030,2375 5030,2485 5010,2505 4975,2505 4970,2500
VCC5V_SPK on BOTTOM "BOTTOM-VCC5V_SPK" (solid, pour order 53): 19 vertices, not listed, extent 4750,2915 5045,3043
GND on BOTTOM "BOTTOM-GND" (solid, pour order 127): 82 vertices, not listed, extent 302,297 5600,3821
VCC5V0_M on BOTTOM "BOTTOM-VCC5V0_M" (solid, pour order 44): 1165,2870 1165,2835 1135,2805 1135,2765 1140,2760 1255,2760 1260,2765 1271,2776 1271,2849 1260,2860 1245,2875 1170,2875 1165,2870
VCC_5V on BOTTOM "BOTTOM-VCC_5V 2" (solid, pour order 98): 29 vertices, not listed, extent 750,520 1012,1240
VDD3V3_PCIE30 on BOTTOM "BOTTOM-VDD3V3_PCIE30" (solid, pour order 22): 2140,1055 2205,1055 2240,1055 2270,1055 2280,1045 2280,1015 2270,1005 2245,1005 2215,1005 2205,995 2165,995 2140,995 2135,1000 2135,1050 2140,1055
VCC_EDP_OUT on BOTTOM "BOTTOM-VCC_EDP_OUT" (solid, pour order 103): 33 vertices, not listed, extent 580,1245 1135,2370
VCC_12V on BOTTOM "BOTTOM-VCC_12V" (solid, pour order 90): 2645,3242 2847,3242 2861,3228 2874,3228 2896,3250 2896,3329 2872,3353 2511,3353 2503,3345 2503,3267 2505,3265 2515,3255 2632,3255 2645,3242
VCC_5V on BOTTOM "BOTTOM-VCC_5V 3" (solid, pour order 104): 38 vertices, not listed, extent 3900,2275 4555,2830
VCC_5V on BOTTOM "BOTTOM-VCC_5V 4" (solid, pour order 116): 44 vertices, not listed, extent 3959,351 5358,1252
VCC_3V8 on BOTTOM "BOTTOM-VCC_3V8" (solid, pour order 65): 25 vertices, not listed, extent 4320,2286 4516,2450
GND_EARTH on BOTTOM "BOTTOM-GND_EARTH" (solid, pour order 124): 37 vertices, not listed, extent 302,3104 2328,3821
VDD3V3_PCIE30 on BOTTOM "BOTTOM-VDD3V3_PCIE30 1" (solid, pour order 94): 26 vertices, not listed, extent 2015,1075 2200,1725
VCC_LVDS_OUT on BOTTOM "BOTTOM-VCC_LVDS_OUT" (solid, pour order 100): 32 vertices, not listed, extent 640,462 1245,740
VDD_3V3 on BOTTOM "BOTTOM-VDD_3V3 1" (solid, pour order 108): 33 vertices, not listed, extent 4166,1215 5347,1773
GND on BOTTOM "BOTTOM-GND 1" (solid, pour order 26): 5070,2525 5105,2525 5115,2515 5115,2430 5110,2425 5075,2425 5070,2420 5070,2375 5065,2370 5045,2370 5040,2375 5040,2495 5070,2525
VCC_LEDK_TX0 on BOTTOM "BOTTOM-VCC_LEDK_TX0" (solid, pour order 19): 1005,1475 1080,1475 1095,1460 1095,1320 1085,1310 1070,1310 1065,1315 1060,1320 1060,1435 1055,1440 1005,1440 1000,1445 1000,1470 1005,1475
VCC_3V3_HUB on BOTTOM "BOTTOM-VCC_3V3_HUB" (solid, pour order 84): 32 vertices, not listed, extent 4190,1880 4450,2109.5
VCC5V0_USB_OTG0 on BOTTOM "BOTTOM-VCC5V0_USB_OTG0 1" (solid, pour order 60): 17 vertices, not listed, extent 5150,3485 5496,3565
VDD_3V3 on BOTTOM "BOTTOM-VDD_3V3 2" (solid, pour order 92): 17 vertices, not listed, extent 585,755 845,1230
VCC_3V3_HUB on BOTTOM "BOTTOM-VCC_3V3_HUB 1" (solid, pour order 89): 17 vertices, not listed, extent 4275,1510 4890,1730
N69887528 on BOTTOM "BOTTOM-N69887528" (solid, pour order 4): 4355,2315 4355,2279 4353,2277 4270,2277 4265,2282 4265,2300 4265,2303 4272,2310 4311,2310 4319,2318 4319,2368 4330,2379 4350,2379 4355,2374 4355,2315
N69864477 on TOP "TOP-N69864477" (solid, pour order 3): 4340,1277 4340,1225 4345,1220 4360,1220 4365,1225 4365,1285 4365,1361 4349,1377 4335,1377 4328,1377 4323,1372 4323,1294 4340,1277
VCC_LEDA_TX0 on TOP "TOP-VCC_LEDA_TX0" (solid, pour order 67): 1005,1135 1200,1135 1215,1150 1215,1215 1215,1235 1210,1240 1055,1240 1010,1240 1000,1230 1000,1210 1000,1140 1005,1135
VCC_5V on TOP "TOP-VCC_5V" (solid, pour order 43): 3540,1190 3540,1125 3540,1110 3576,1074 3576,1063 3582.5,1056.5 3641.5,1056.5 3645,1060 3645,1080 3645,1155 3625,1175 3625,1195 3620,1200 3550,1200 3540,1190
GND on TOP "TOP-GND" (solid, pour order 42): 4414,645 4444,645 4458,631 4615,631 4625,641 4723,641 4730,634 4730,604 4714,588 4672,588 4663,597 4414,597 4409,602 4409,640 4414,645
VCC5V_SPK on TOP "TOP-VCC5V_SPK" (solid, pour order 47): 22 vertices, not listed, extent 4500,2935 4810,3045
VDD3V3_PCIE30 on TOP "TOP-VDD3V3_PCIE30" (solid, pour order 81): 22 vertices, not listed, extent 1857,1355 2120,1715
VDD_3V3 on TOP "TOP-VDD_3V3" (solid, pour order 55): 17 vertices, not listed, extent 3115,600 3235,870
GND_IN on TOP "TOP-GND_IN" (solid, pour order 57): 1004,691 1016,691 1024,683 1024,619 1009,604 796,604 796,674 805,683 996,683 1004,691
VCC5V0_USB_OTG0 on TOP "TOP-VCC5V0_USB_OTG0" (solid, pour order 106): 35 vertices, not listed, extent 5183,3042 5554,3620
VCC_5V on TOP "TOP-VCC_5V 1" (solid, pour order 78): 17 vertices, not listed, extent 5280,790 5580,905
PHY1_REG_OUT on TOP "TOP-PHY1_REG_OUT" (solid, pour order 33): 20 vertices, not listed, extent 2720,1565 2830,1785
VCC2V8_DVP on TOP "TOP-VCC2V8_DVP" (solid, pour order 14): 2175,730 2205,730 2210,730 2215,725 2215,670 2210,665 2150,605 2115,605 2110,610 2110,655 2120,665 2150,665 2170,685 2170,725 2175,730
GND on TOP "TOP-GND 1" (solid, pour order 30): 18 vertices, not listed, extent 1325,740 1490,820
VCC_LVDS_OUT on TOP "TOP-VCC_LVDS_OUT" (solid, pour order 54): 18 vertices, not listed, extent 1165,675 1385,800
VCC_EDP_OUT on TOP "TOP-VCC_EDP_OUT" (solid, pour order 85): 26 vertices, not listed, extent 505,925 640,1310
N69812831 on TOP "TOP-N69812831" (solid, pour order 51): 21 vertices, not listed, extent 855,1265 1020,1425
VCCIO_PHY1 on TOP "TOP-VCCIO_PHY1" (solid, pour order 7): 19 vertices, not listed, extent 2680,1443 2745,1595
VCC5V0_USB2 on TOP "TOP-VCC5V0_USB2" (solid, pour order 75): 18 vertices, not listed, extent 4565,375 4710,585
VCC12V_DCIN on TOP "TOP-VCC12V_DCIN" (solid, pour order 120): 64 vertices, not listed, extent 307,340 1135,3660
VDD10_PHY0 on TOP "TOP-VDD10_PHY0" (solid, pour order 29): 1790,1615 1870,1615 1875,1610 1875,1525 1870,1520 1785,1520 1780,1525 1775,1530 1775,1605 1785,1615 1790,1615
GND on TOP "TOP-GND 2" (solid, pour order 18): 1945,1460 2105,1460 2110,1455 2110,1420 2105,1415 1945,1415 1940,1420 1940,1455 1945,1460
VCC5V0_USB_OTG0 on TOP "TOP-VCC5V0_USB_OTG0 1" (solid, pour order 2): 20 vertices, not listed, extent 5155,3510 5250,3620
VCC_3V3_HUB on TOP "TOP-VCC_3V3_HUB" (solid, pour order 74): 46 vertices, not listed, extent 4185,1540 4375,1905
VCC5V0_USB3 on TOP "TOP-VCC5V0_USB3" (solid, pour order 82): 20 vertices, not listed, extent 4080,370 4250,845
VDD_3V3 on TOP "TOP-VDD_3V3 1" (solid, pour order 68): 23 vertices, not listed, extent 723,530 860,835
VCC5V0_USB_HOST1 on TOP "TOP-VCC5V0_USB_HOST1" (solid, pour order 69): 28 vertices, not listed, extent 3811,2916 3940,3370
VCC_5V on TOP "TOP-VCC_5V 2" (solid, pour order 38): 4450,2905 4550,2905 4565,2890 4565,2820 4550,2805 4445,2805 4440,2810 4440,2830 4440,2895 4450,2905
VCC_5V on TOP "TOP-VCC_5V 3" (solid, pour order 21): 4505,580 4505,555 4495,545 4495,510 4485,500 4415,500 4405,510 4405,580 4410,585 4500,585 4505,580
VDD3V3_PCIE30 on TOP "TOP-VDD3V3_PCIE30 1" (solid, pour order 72): 21 vertices, not listed, extent 2015,930 2285,1120
VCC_3V8 on TOP "TOP-VCC_3V8" (solid, pour order 50): 18 vertices, not listed, extent 4151,2660 4290,2840
VCC_3V8 on TOP "TOP-VCC_3V8 1" (solid, pour order 36): 24 vertices, not listed, extent 4415,2270 4585,2430
VCC_5V on TOP "TOP-VCC_5V 4" (solid, pour order 12): 4050,973 4050,910 4055,905 4095,905 4105,895 4135,895 4140,900 4140,945 4115,970 4115,975 4115,982 4059,982 4050,973
VCC_12V on TOP "TOP-VCC_12V" (solid, pour order 80): 895,2730 895,2565 855,2525 745,2525 735,2535 735,2675 735,2735 740,2740 885,2740 895,2730
VCC5V_SYS on TOP "TOP-VCC5V_SYS" (solid, pour order 77): 19 vertices, not listed, extent 2565,2849 2792,3036
VBAT_WL_1T1R on TOP "TOP-VBAT_WL_1T1R" (solid, pour order 28): 5115,1740 5115,1690 5105,1680 5105,1600 5100,1595 5040,1595 5035,1600 5035,1670 5070,1705 5070,1740 5075,1745 5110,1745 5115,1740
N69814391 on TOP "TOP-N69814391" (solid, pour order 17): 1565,1325 1565,1215 1560,1210 1533,1210 1529,1214 1529,1291 1515,1305 1434,1305 1430,1309 1430,1330 1435,1335 1555,1335 1565,1325
VDD_3V3 on TOP "TOP-VDD_3V3 2" (solid, pour order 73): 41 vertices, not listed, extent 1580,1189 1824,1523
VCC5V0_M on TOP "TOP-VCC5V0_M" (solid, pour order 62): 18 vertices, not listed, extent 1040,2670 1260,2815
VCC_LVDS_OUT_ on TOP "TOP-VCC_LVDS_OUT_" (solid, pour order 0): 1120,660 1125,655 1195,655 1200,660 1200,680 1195,685 1165,685 1165,695 1150,710 1140,710 1130,710 1115,710 1110,705 1110,670 1120,660
VDD_3V3 on TOP "TOP-VDD_3V3 3" (solid, pour order 8): 2545,1298 2545,1251 2550,1246 2602,1246 2602,1347 2602,1370 2598,1374 2566,1374 2562,1370 2562,1332 2553,1323 2553,1306 2545,1298
VCC_3V8 on TOP "TOP-VCC_3V8 2" (solid, pour order 52): 18 vertices, not listed, extent 4025,2195.5 4115,2430
VCC5V_SPK on TOP "TOP-VCC5V_SPK 1" (solid, pour order 39): 17 vertices, not listed, extent 4930,2911 5090,3040
VCC_5V on TOP "TOP-VCC_5V 5" (solid, pour order 41): 1285,1175 1425,1175 1430,1170 1430,1140 1430,1090 1368,1090 1361,1097 1275,1097 1270,1102 1270,1160 1285,1175
N69912226 on TOP "TOP-N69912226" (solid, pour order 49): 3690,1195 3765,1195 3790,1195 3805,1180 3805,1090 3805,1075 3800,1070 3695,1070 3690,1075 3685,1080 3685,1190 3690,1195
VBAT_WL_1T1R on TOP "TOP-VBAT_WL_1T1R 1" (solid, pour order 46): 4695,1145 4830,1145 4870,1185 4935,1185 4945,1175 4945,1110 4935,1100 4775,1100 4760,1115 4695,1115 4690,1120 4690,1140 4695,1145
N69922778 on TOP "TOP-N69922778" (solid, pour order 64): 1245,1070 1260,1055 1266,1049 1360,1049 1374,1035 1430,1035 1430,985 1425,980 1205,980 1175,1010 1150,1035 1150,1090 1155,1095 1220,1095 1245,1070
VDD_3V3 on TOP "TOP-VDD_3V3 4" (solid, pour order 6): 4221,1630 4180,1630 4170,1620 4170,1532 4171,1531 4211,1531 4230,1550 4230,1621 4221,1630
VCC_5V on TOP "TOP-VCC_5V 6" (solid, pour order 34): 1280,1375 1280,1310 1290,1300 1365,1300 1370,1305 1370,1340 1370,1355 1270,1455 1250,1455 1245,1450 1245,1420 1245,1410 1280,1375
VCC5V0_USB1 on TOP "TOP-VCC5V0_USB1" (solid, pour order 24): 4955,1085 4955,1030 4955,1005 4960,1000 5040,1000 5045,1005 5045,1030 5045,1085 5040,1090 4960,1090 4955,1085
VCC_LVDS_OUT_ on TOP "TOP-VCC_LVDS_OUT_ 1" (solid, pour order 87): 22 vertices, not listed, extent 460,1390 760,1565
VCC_5V on TOP "TOP-VCC_5V 7" (solid, pour order 97): 39 vertices, not listed, extent 585,895 915,1425
VDD_3V3 on TOP "TOP-VDD_3V3 5" (solid, pour order 1): 2783,1375 2755,1375 2746,1366 2746,1261 2750.5,1256.5 2774.5,1256.5 2777,1259 2777,1300 2780,1303 2788,1303 2790.5,1305.5 2792,1307 2792,1366 2783,1375
GND_IN on TOP "TOP-GND_IN 1" (solid, pour order 37): 710,2780 638,2780 629,2789 629,2938 633,2942 683.5,2942 683.5,2941.5 689,2936 689,2892 708,2873 714,2867 714,2784 710,2780
GND on TOP "TOP-GND 3" (solid, pour order 128): 82 vertices, not listed, extent 302,297 5600,3821
VDD_3V3 on TOP "TOP-VDD_3V3 6" (solid, pour order 48): 2970,1255 2965,1260 2965,1300 2965,1315 2965,1376 2963,1378 2963,1563 2976,1576 3004,1576 3010,1570 3010,1365 3010,1260 3005,1255 2970,1255
N69812073 on TOP "TOP-N69812073" (solid, pour order 40): 24 vertices, not listed, extent 2848,2876 2961,3036
VCC5V_SYS on TOP "TOP-VCC5V_SYS 1" (solid, pour order 110): 32 vertices, not listed, extent 1179,3259 2497,3816
VCC_12V on TOP "TOP-VCC_12V 1" (solid, pour order 58): 19 vertices, not listed, extent 775,1404 1022.5,1510
N69864462 on TOP "TOP-N69864462" (solid, pour order 11): 21 vertices, not listed, extent 4180,1289 4270,1400
VCC_5V on TOP "TOP-VCC_5V 8" (solid, pour order 63): 34 vertices, not listed, extent 4000,2752 4145,3016
VCC2V8_DVP on TOP "TOP-VCC2V8_DVP 1" (solid, pour order 16): 2940,765 2940,740 2865,665 2865,610 2870,605 2895,605 2900,610 2900,650 2970,720 2990,740 2990,765 2985,770 2965,770 2945,770 2940,765
N69927169 on TOP "TOP-N69927169" (solid, pour order 31): 1325,665 1330,660 1430,660 1435,655 1435,615 1430,610 1250,610 1240,620 1240,660 1245,665 1325,665
VCC5V0_USB_HOST2 on TOP "TOP-VCC5V0_USB_HOST2" (solid, pour order 88): 23 vertices, not listed, extent 3810,3065 4135,3480
VCC_12V on TOP "TOP-VCC_12V 2" (solid, pour order 70): 39 vertices, not listed, extent 2769,2973 2964.5,3281
GND_IN on TOP "TOP-GND_IN 2" (solid, pour order 35): 700,820 760,820 770,810 770,780 770,772 707,709 702,709 660,709 646,723 646,812 654,820 700,820
VCC_5V on TOP "TOP-VCC_5V 9" (solid, pour order 114): 26 vertices, not listed, extent 1584,355 4058,595
PHY0_REG_OUT on TOP "TOP-PHY0_REG_OUT" (solid, pour order 23): 20 vertices, not listed, extent 1725,1660 1875,1795
N69300963 on TOP "TOP-N69300963" (solid, pour order 83): 20 vertices, not listed, extent 698,2780 875,3130
VCC3V3_PHY0 on TOP "TOP-VCC3V3_PHY0" (solid, pour order 5): 17 vertices, not listed, extent 1460,1935 1580,2010
VDD_3V3 on TOP "TOP-VDD_3V3 7" (solid, pour order 45): 20 vertices, not listed, extent 5120,1635 5225,1795
GND_IN on TOP "TOP-GND_IN 3" (solid, pour order 66): 795,3252 845,3202 859,3188 859,3147 857,3145 715,3145 682,3145 668,3159 668,3262 689,3283 710,3283 764,3283 795,3252
VDD10_PHY1 on TOP "TOP-VDD10_PHY1" (solid, pour order 27): 18 vertices, not listed, extent 2785,1515 2915,1650
GND on TOP "TOP-GND 4" (solid, pour order 25): 23 vertices, not listed, extent 3635,1205 3785,1302
VCC5V0_USB1 on TOP "TOP-VCC5V0_USB1 1" (solid, pour order 76): 22 vertices, not listed, extent 5043,370 5212,858
VCC_3V8 on TOP "TOP-VCC_3V8 3" (solid, pour order 61): 4975,2425 4975,2330 4970,2325 4915,2325 4910,2320 4910,2275 4915,2270 5025,2270 5065,2270 5070,2275 5070,2425 5065,2430 5025,2430 4980,2430 4975,2425
VCC_5V on TOP "TOP-VCC_5V 10" (solid, pour order 10): 5020,1150 5040,1150 5046,1150 5052,1156 5052,1232 5029,1255 4975,1255 4965,1255 4960,1250 4960,1215 4970,1205 5000,1205 5015,1190 5015,1155 5020,1150
no net on L3-POW (solid, pour order 112): 47 vertices, not listed, extent 4016,333 5404,1283
no net on L3-POW (solid, pour order 117): 61 vertices, not listed, extent 3841,2206.5 5072.5,2875
no net on L3-POW (solid, pour order 105): 30 vertices, not listed, extent 568,1161 1046,2347.5
no net on L3-POW (solid, pour order 122): 46 vertices, not listed, extent 307,372.5 854,3815
no net on L3-POW (solid, pour order 109): 39 vertices, not listed, extent 3958,2157.5 5072.5,2553
no net on L3-POW (solid, pour order 111): 17 vertices, not listed, extent 874,351 1696,711
no net on L3-POW (solid, pour order 93): 26 vertices, not listed, extent 1784,1541 2077,1947.5
no net on L3-POW (solid, pour order 119): 902.61,3313 860,3355.61 860,3807 869,3816 2316,3816 2321,3816 2330,3807 2330,3344 2299,3313 902.61,3313
no net on L3-POW (solid, pour order 125): 82 vertices, not listed, extent 307,302 5595,3816
no net on L2-GND (solid, pour order 107): 30 vertices, not listed, extent 725,1074 1361,1433
no net on L2-GND (solid, pour order 126): 82 vertices, not listed, extent 307,302 5595,3816
no net on L2-GND (solid, pour order 113): 24 vertices, not listed, extent 307,333 1085,986
no net on L2-GND (solid, pour order 101): 29 vertices, not listed, extent 2315,2873 2710,3352
no net on L2-GND (solid, pour order 96): 43 vertices, not listed, extent 1484.8,1622 2038,1987.5
no net on L2-GND (solid, pour order 123): 66 vertices, not listed, extent 307,1361 2562,3805
no net on L2-GND (solid, pour order 99): 33 vertices, not listed, extent 4903,2471 5356,3099
no net on L2-GND (solid, pour order 118): 33 vertices, not listed, extent 714,2660 1277,3710
no net on L2-GND (solid, pour order 79): 23 vertices, not listed, extent 1482.5,1917.5 1847.5,2047.5
no net on L2-GND (solid, pour order 115): 31 vertices, not listed, extent 4817.5,1192.5 5307.5,2237.5
no net on L2-GND (solid, pour order 121): 119 vertices, not listed, extent 576,334 4141,1335

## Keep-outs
TOP:
  region: 1853,1943 1853,1929 1860,1929 1860,1943 1853,1943
L2-GND:
  region: 4690,905 4745,905 4755,905 4760,910 4960,910 4965,915 4980,915 5110,915 5115,910 5115,845 5110,840 4960,840 4955,845 4755,845 4750,850 4690,850 4685,855 4685,900 4690,905
Multi-Layer:
  region: 3783.01,5643.72 3781.08,5663.32 3775.37,5682.17 3766.08,5699.55 3753.58,5714.77 3738.36,5727.27 3720.98,5736.56 3702.13,5742.27 3682.53,5744.2 3662.93,5742.27 3644.08,5736.56 3632.5,5730.37 3626.71,5727.27 3611.48,5714.77 3598.98,5699.55 3589.7,5682.17 3583.98,5663.32 3582.05,5643.72 3583.98,5624.12 3589.7,5605.27 3598.98,5587.89 3611.48,5572.67 3626.71,5560.17 3632.5,5557.07 3644.08,5550.89 3662.93,5545.17 3682.53,5543.24 3702.13,5545.17 3720.98,5550.89 3738.36,5560.17 3753.58,5572.67 3766.08,5587.89 3775.37,5605.27 3781.08,5624.12 3783.01,5643.72
  region: 809.11,5643.72 807.18,5663.32 801.46,5682.17 792.18,5699.55 779.68,5714.77 764.45,5727.27 747.08,5736.56 728.23,5742.27 708.63,5744.2 689.02,5742.27 670.17,5736.56 658.6,5730.37 652.8,5727.27 637.57,5714.77 625.08,5699.55 615.79,5682.17 610.07,5663.32 608.14,5643.72 610.07,5624.12 615.79,5605.27 625.08,5587.89 637.57,5572.67 652.8,5560.17 658.6,5557.07 670.17,5550.89 689.02,5545.17 708.63,5543.24 728.23,5545.17 747.08,5550.89 764.45,5560.17 779.68,5572.67 792.18,5587.89 801.46,5605.27 807.18,5624.12 809.11,5643.72
  region: 3090,5749 3090,5692 3236,5692 3236,5749 3090,5749

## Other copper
TOP:
  drawing of 443 lines, arcs and shapes, not listed
BOTTOM:
  drawing of 196 lines, arcs and shapes, not listed
Multi-Layer:
  dashed: 4990,3940 5690,3940 5860,3770 5860,1695 5695,1530 4155,1530 3885,1800 3885,3770 4065,3950 4980,3950 4990,3940
  text "PARTITION_2" at 4872.5,2740 h25

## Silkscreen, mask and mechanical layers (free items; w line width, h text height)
OUTLINE:
  lines w1: 292,327 ccw(c332,327) 332,287 5570,287 ccw(c5570,327) 5610,327 5610,3791 ccw(c5570,3791) 5570,3831 4436,3831 4309,3831 332,3831 ccw(c332,3791) 292,3791 292,327
L2-GND:
  drawing of 981 lines, arcs and shapes, not listed
L3-POW:
  drawing of 1317 lines, arcs and shapes, not listed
